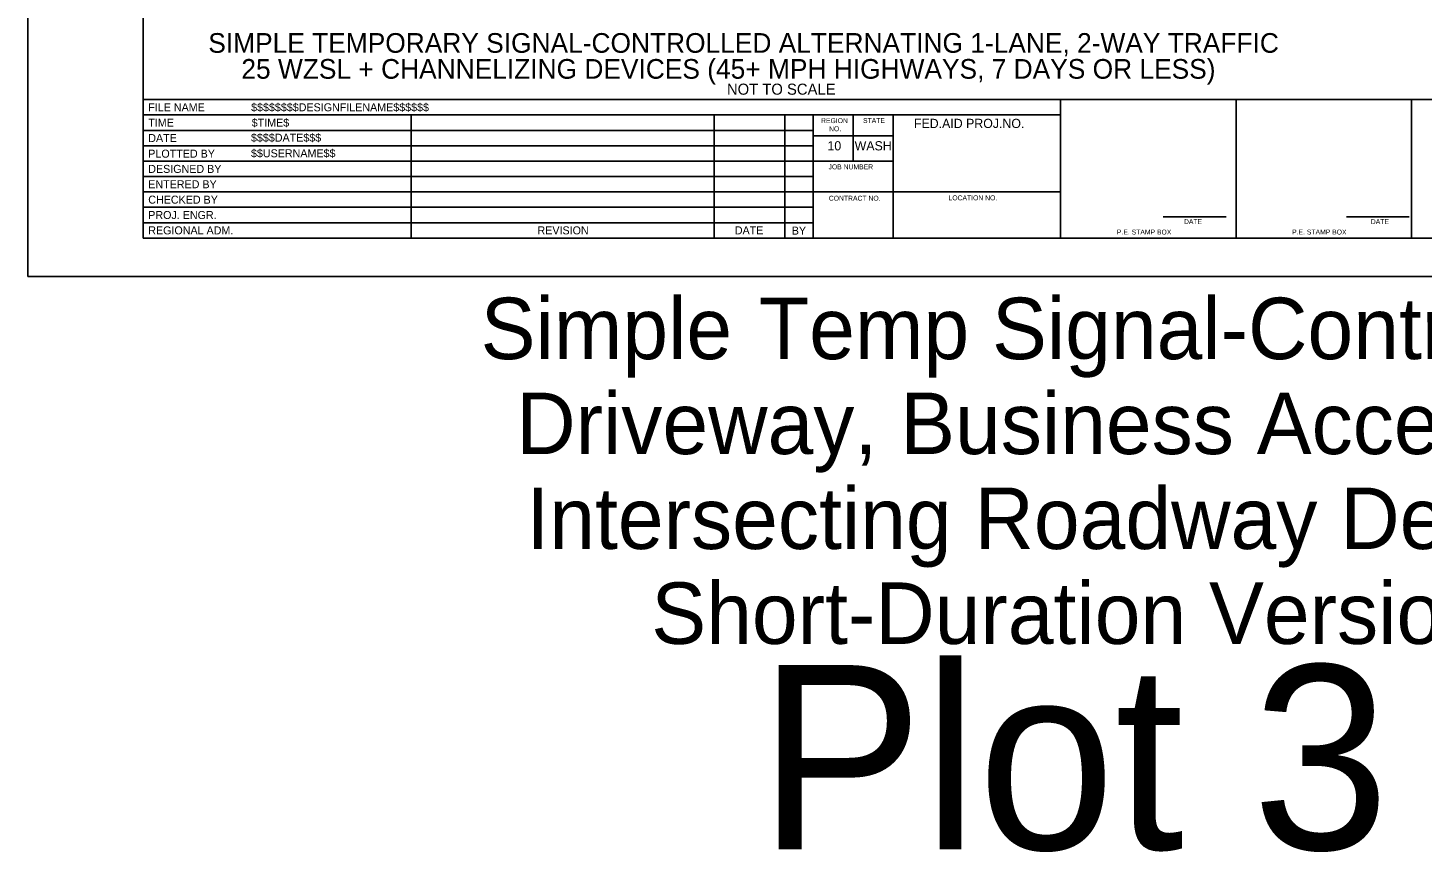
# Model space of a CAD drawing. Extents: x 99979.8 to 100075.7, y 99995 to 100010.7.
# Drawn here: x 100039.06 to 100050.4, y 99995.01 to 100001.71 of the extents above; entities that cross this region are included whole.
import ezdxf

# ---------------------------------------------------------------- set-up
doc = ezdxf.new("R2010")
doc.units = 0
for name, color, linetype in [('SH_DE_DetailHeading1Text', 7, 'Continuous'), ('SH_GI_PlotLimits', 7, 'Continuous'), ('SH_GI_SheetBorder', 7, 'Continuous'), ('SH_GI_SheetLocationText', 7, 'Continuous'), ('SH_GI_SheetTextInCells', 7, 'Continuous'), ('SH_GI_TitleBlockText', 7, 'Continuous')]:
    doc.layers.add(name, color=color, linetype=linetype)

msp = doc.modelspace()

# ---------------------------------------------------------------- linework, layer by layer
at = {"layer": 'SH_GI_PlotLimits'}
msp.add_lwpolyline([(100039.062, 99999.687), (100056.062, 99999.687), (100056.062, 100010.687), (100039.062, 100010.687)], close=True, dxfattribs=at)
at = {"layer": 'SH_GI_SheetBorder'}
for p, q in [((100040, 100010.375), (100040, 100000)), ((100040, 100001.126), (100055.75, 100001.126)), ((100047.457, 100000), (100047.457, 100001.126)), ((100048.883, 100000), (100048.883, 100001.126)), ((100050.309, 100001.126), (100050.309, 100000)), ((100040, 100001.001), (100047.457, 100001.001)), ((100042.179, 100001.001), (100042.179, 100000)), ((100044.641, 100001.001), (100044.641, 100000)), ((100045.216, 100001.001), (100045.216, 100000)), ((100045.445, 100001.001), (100045.445, 100000)), ((100045.772, 100000.625), (100045.772, 100001.001)), ((100046.096, 100000), (100046.096, 100001.001)), ((100040, 100000.876), (100042.182, 100000.876)), ((100042.182, 100000.876), (100045.447, 100000.876)), ((100046.096, 100000.831), (100045.447, 100000.831)), ((100040, 100000.751), (100042.182, 100000.751)), ((100042.182, 100000.751), (100045.447, 100000.751)), ((100040, 100000.625), (100045.447, 100000.625)), ((100046.096, 100000.625), (100045.447, 100000.625)), ((100040, 100000.5), (100045.447, 100000.5)), ((100040, 100000.375), (100045.447, 100000.375)), ((100047.457, 100000.375), (100045.447, 100000.375)), ((100040, 100000.25), (100045.447, 100000.25)), ((100040, 100000.125), (100045.447, 100000.125)), ((100048.29, 100000.173), (100048.802, 100000.173)), ((100049.78, 100000.173), (100050.291, 100000.173)), ((100040, 100000), (100055.75, 100000))]:
    msp.add_line(p, q, dxfattribs=at)

# ---------------------------------------------------------------- texts
at = {"layer": 'SH_DE_DetailHeading1Text'}
for s, height, p in [('SIMPLE TEMPORARY SIGNAL-CONTROLLED ALTERNATING 1-LANE, 2-WAY TRAFFIC', 0.16, (100040.529, 100001.507)), ('25 WZSL + CHANNELIZING DEVICES (45+ MPH HIGHWAYS, 7 DAYS OR LESS)', 0.16, (100040.798, 100001.296)), ('NOT TO SCALE', 0.09, (100044.745, 100001.166))]:
    msp.add_text(s, height=height, rotation=360, dxfattribs=at).set_placement(p)
at = {"layer": 'SH_GI_SheetLocationText'}
for s, height, p in [('Simple', 0.5, (100042.743, 99999.015)), (' Temp Signal-Controlled', 0.5, (100044.819, 99999.015)), ('Driveway, Business Access, &', 0.5, (100043.032, 99998.243)), ('Intersecting Roadway Details', 0.5, (100043.115, 99997.471)), ('Short-Duration Version', 0.5, (100044.13, 99996.699)), ('Plot 3', 1.5, (100045.001, 99995.027))]:
    msp.add_text(s, height=height, dxfattribs=at).set_placement(p)
at = {"layer": 'SH_GI_SheetTextInCells'}
for s, height, p in [('FILE NAME', 0.0651, (100040.041, 100001.031)), ('TIME', 0.0651, (100040.041, 100000.906)), ('REGION', 0.04, (100045.51, 100000.935)), ('NO.', 0.04, (100045.575, 100000.869)), ('STATE', 0.04, (100045.851, 100000.936)), ('FED.AID PROJ.NO.', 0.07506, (100046.265, 100000.895)), ('DATE', 0.0651, (100040.041, 100000.781)), ('10', 0.0751, (100045.562, 100000.713)), ('WASH', 0.0751, (100045.783, 100000.713)), ('PLOTTED BY', 0.0651, (100040.041, 100000.654)), ('DESIGNED BY', 0.06505, (100040.041, 100000.53)), ('JOB NUMBER', 0.04, (100045.571, 100000.559)), ('ENTERED BY', 0.0651, (100040.041, 100000.405)), ('CHECKED BY', 0.0651, (100040.041, 100000.28)), ('CONTRACT NO.', 0.04003, (100045.573, 100000.304)), ('LOCATION NO.', 0.04003, (100046.546, 100000.307)), ('PROJ. ENGR.', 0.06505, (100040.041, 100000.155)), ('REGIONAL ADM.', 0.06505, (100040.041, 100000.03)), ('REVISION', 0.0651, (100043.205, 100000.03)), ('DATE', 0.0651, (100044.809, 100000.03)), ('BY', 0.0651, (100045.272, 100000.028)), ('DATE', 0.04, (100048.46, 100000.114)), ('DATE', 0.04, (100049.979, 100000.114)), ('P.E. STAMP BOX', 0.04003, (100047.915, 100000.029)), ('P.E. STAMP BOX', 0.04003, (100049.339, 100000.029))]:
    msp.add_text(s, height=height, dxfattribs=at).set_placement(p)
at = {"layer": 'SH_GI_TitleBlockText'}
for s, height, p in [('$$$$$$$$DESIGNFILENAME$$$$$$', 0.06505, (100040.877, 100001.031)), ('$TIME$', 0.0651, (100040.882, 100000.906)), ('$$$$DATE$$$', 0.06505, (100040.876, 100000.784)), ('$$USERNAME$$', 0.06505, (100040.876, 100000.657))]:
    msp.add_text(s, height=height, dxfattribs=at).set_placement(p)

doc.saveas('drawing.dxf')
